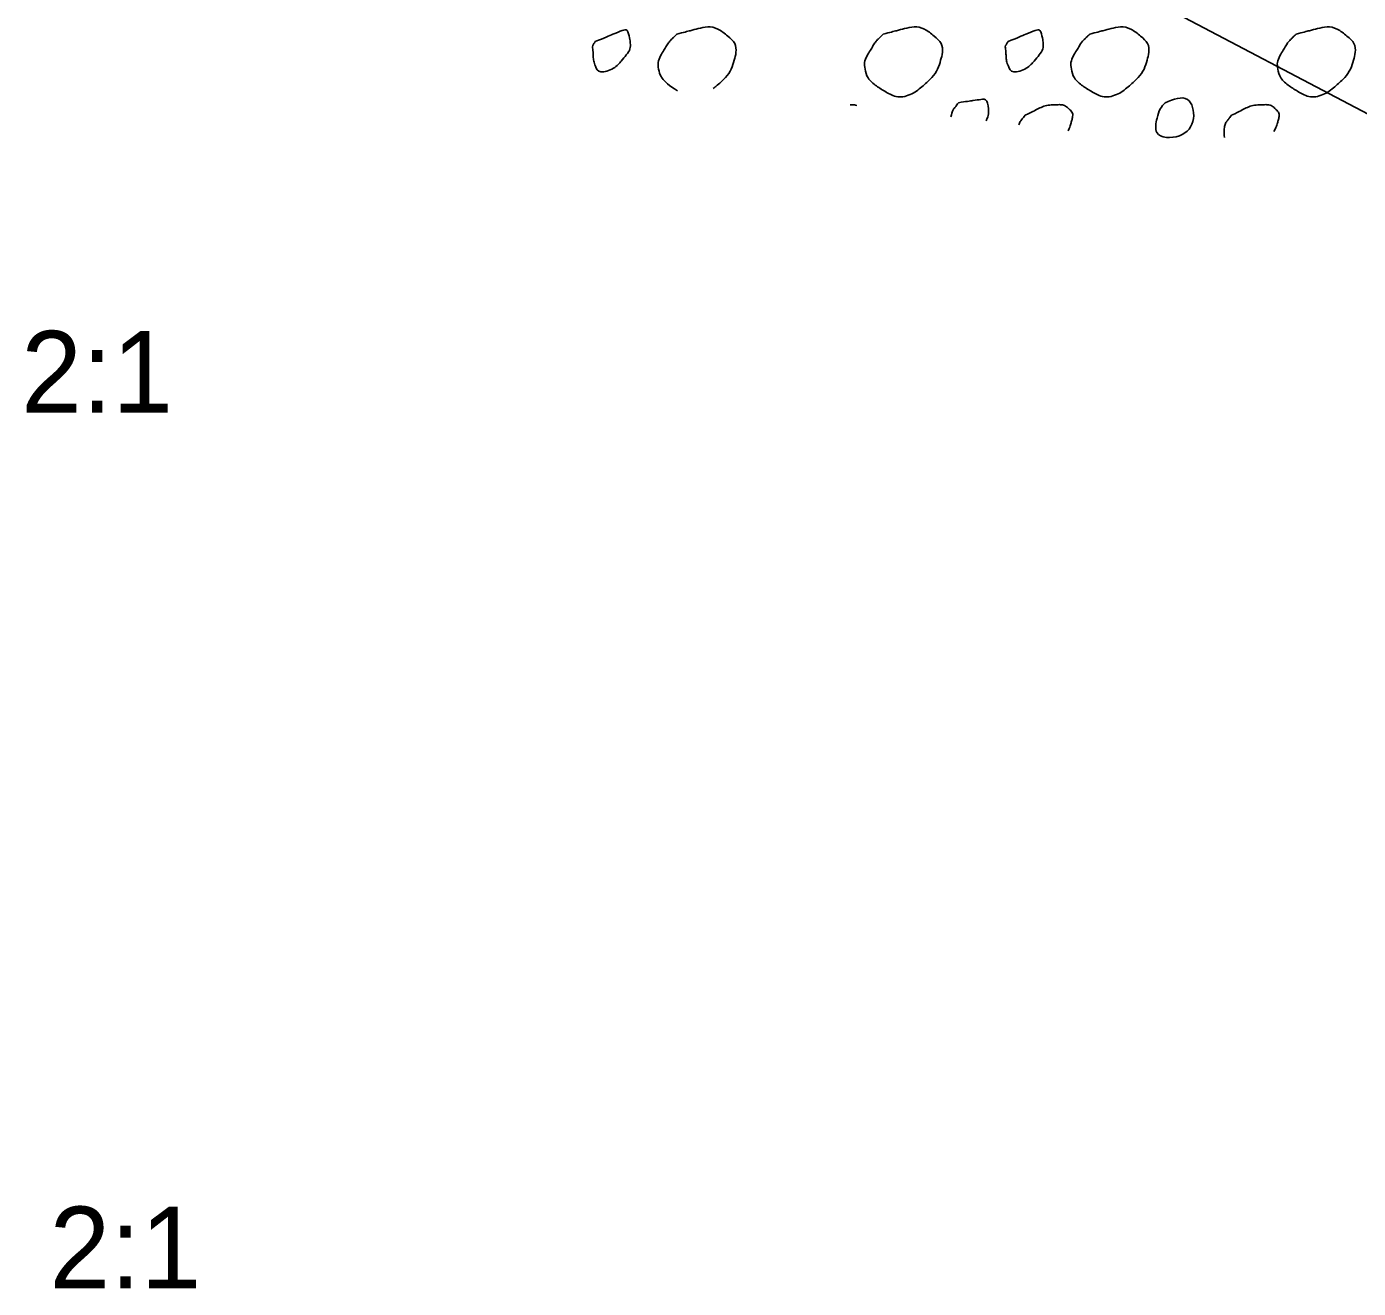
# Model space of a CAD drawing. Extents: x 0 to 486, y 0 to 220.
# Drawn here: x 127.82 to 150.63, y 118.93 to 140.54 of the extents above; entities that cross this region are included whole.
import ezdxf

# ---------------------------------------------------------------- set-up
doc = ezdxf.new("R2010")
doc.units = 0
doc.layers.add('GE_X_Alignment_100_Cardinal_Points', color=7, linetype='Continuous')
doc.layers.add('SV_X_Shot_Marker', color=7, linetype='Continuous')

msp = doc.modelspace()

# ---------------------------------------------------------------- linework, layer by layer
at = {"layer": 'GE_X_Alignment_100_Cardinal_Points'}
msp.add_line((176.497, 125.503), (130.5, 149.727), dxfattribs=at)
at = {"layer": 'SV_X_Shot_Marker'}
for points in [[(138.953, 140.409), (139.072, 140.441), (139.191, 140.472), (139.309, 140.503), (139.482, 140.547), (139.657, 140.516), (139.83, 140.371), (139.964, 140.259), (139.973, 140.092), (139.938, 139.968), (139.893, 139.812), (139.794, 139.663), (139.642, 139.533), (139.62, 139.515), (139.597, 139.497), (139.574, 139.482)], [(142.489, 140.409), (142.608, 140.441), (142.726, 140.472), (142.845, 140.503), (143.018, 140.547), (143.193, 140.516), (143.366, 140.371), (143.5, 140.259), (143.509, 140.092), (143.473, 139.968), (143.428, 139.812), (143.329, 139.663), (143.178, 139.533), (142.988, 139.371), (142.724, 139.307), (142.529, 139.423), (142.372, 139.516), (142.205, 139.656), (142.175, 139.821), (142.156, 139.924), (142.21, 140.043), (142.27, 140.139), (142.313, 140.208), (142.351, 140.277), (142.408, 140.332), (142.435, 140.358), (142.462, 140.383), (142.489, 140.409)], [(146.025, 140.409), (146.144, 140.441), (146.262, 140.472), (146.381, 140.503), (146.554, 140.547), (146.728, 140.516), (146.902, 140.371), (147.036, 140.259), (147.045, 140.092), (147.009, 139.968), (146.964, 139.812), (146.865, 139.663), (146.713, 139.533), (146.523, 139.371), (146.259, 139.307), (146.065, 139.423), (145.907, 139.516), (145.741, 139.656), (145.711, 139.821), (145.692, 139.924), (145.745, 140.043), (145.806, 140.139), (145.849, 140.208), (145.887, 140.277), (145.944, 140.332), (145.971, 140.358), (145.998, 140.383), (146.025, 140.409)], [(149.561, 140.409), (149.679, 140.441), (149.798, 140.472), (149.917, 140.503), (150.09, 140.547), (150.264, 140.516), (150.438, 140.371), (150.572, 140.259), (150.581, 140.092), (150.545, 139.968), (150.5, 139.812), (150.401, 139.663), (150.249, 139.533), (150.059, 139.371), (149.795, 139.307), (149.601, 139.423), (149.443, 139.516), (149.277, 139.656), (149.247, 139.821), (149.228, 139.924), (149.281, 140.043), (149.342, 140.139), (149.385, 140.208), (149.423, 140.277), (149.48, 140.332), (149.507, 140.358), (149.534, 140.383), (149.561, 140.409)], [(137.554, 140.283), (137.713, 140.347), (137.871, 140.416), (138.029, 140.476), (138.107, 140.506), (138.148, 140.332), (138.155, 140.258), (138.164, 140.158), (138.088, 140.054), (138.006, 139.955), (137.894, 139.821), (137.614, 139.723), (137.556, 139.871), (137.525, 139.949), (137.52, 140.03), (137.517, 140.111), (137.515, 140.151), (137.5, 140.196), (137.521, 140.232), (137.532, 140.25), (137.543, 140.266), (137.554, 140.283)], [(138.966, 139.439), (138.817, 139.532), (138.668, 139.665), (138.639, 139.821), (138.62, 139.924), (138.674, 140.043), (138.734, 140.139), (138.777, 140.208), (138.816, 140.277), (138.873, 140.332), (138.899, 140.358), (138.926, 140.383), (138.953, 140.409)], [(144.626, 140.283), (144.784, 140.347), (144.943, 140.416), (145.101, 140.476), (145.179, 140.506), (145.22, 140.332), (145.227, 140.258), (145.236, 140.158), (145.16, 140.054), (145.078, 139.955), (144.966, 139.821), (144.685, 139.723), (144.628, 139.871), (144.597, 139.949), (144.592, 140.03), (144.588, 140.111), (144.587, 140.151), (144.572, 140.196), (144.593, 140.232), (144.603, 140.25), (144.615, 140.266), (144.626, 140.283)], [(141.923, 139.202), (141.926, 139.202), (141.929, 139.202), (141.933, 139.202), (141.968, 139.203), (142.003, 139.2), (142.038, 139.188)], [(143.648, 138.996), (143.66, 139.045), (143.669, 139.097), (143.7, 139.135), (143.727, 139.169), (143.753, 139.203), (143.78, 139.236)], [(143.78, 139.236), (143.907, 139.255), (144.035, 139.275), (144.162, 139.292), (144.275, 139.307), (144.302, 139.062), (144.266, 138.964), (144.261, 138.951), (144.255, 138.938), (144.249, 138.925)], [(144.918, 139.02), (145.001, 139.061), (145.084, 139.103), (145.168, 139.145), (145.259, 139.19), (145.369, 139.199), (145.468, 139.202), (145.542, 139.204), (145.613, 139.187), (145.679, 139.121), (145.74, 139.061), (145.731, 138.981), (145.713, 138.918), (145.698, 138.864), (145.68, 138.809), (145.653, 138.757)], [(148.453, 139.02), (148.537, 139.061), (148.62, 139.103), (148.703, 139.145), (148.795, 139.19), (148.904, 139.199), (149.004, 139.202), (149.078, 139.204), (149.149, 139.187), (149.215, 139.121), (149.276, 139.061), (149.267, 138.981), (149.249, 138.918), (149.232, 138.859), (149.213, 138.799), (149.18, 138.742)], [(144.811, 138.858), (144.818, 138.881), (144.829, 138.903), (144.843, 138.923), (144.868, 138.956), (144.893, 138.987), (144.918, 139.02)], [(148.335, 138.639), (148.328, 138.667), (148.327, 138.695), (148.328, 138.723), (148.329, 138.789), (148.337, 138.868), (148.379, 138.923), (148.404, 138.956), (148.428, 138.987), (148.453, 139.02)]]:
    msp.add_open_spline(points, degree=3, dxfattribs=at)
msp.add_spline([(147.316, 139.236), (147.698, 139.292), (147.802, 138.964), (147.562, 138.67), (147.175, 138.726), (147.178, 138.972), (147.236, 139.135), (147.316, 139.236)], degree=3, dxfattribs=at)

# ---------------------------------------------------------------- texts
at = {"layer": 'GE_X_Alignment_100_Cardinal_Points'}
for p in [(127.721, 133.927), (128.206, 118.927)]:
    msp.add_text('2:1', height=1.4, rotation=0, dxfattribs=at).set_placement(p)

doc.saveas('drawing.dxf')
